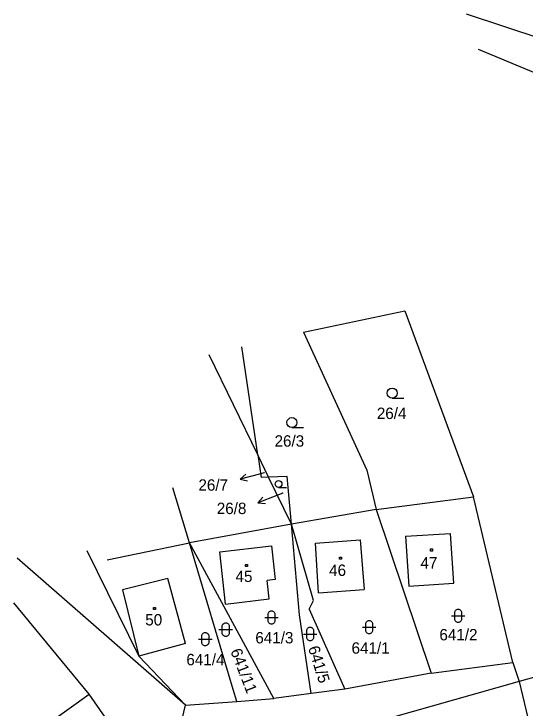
# Model space of a CAD drawing. Extents: x -866656 to -858817, y -1041816 to -1038653.
# Drawn here: x -862846 to -862769.6, y -1039578.3 to -1039474.6 of the extents above; entities that cross this region are included whole.
import ezdxf

# ---------------------------------------------------------------- set-up
doc = ezdxf.new("R2010")
doc.units = 0
doc.layers.add('Vrstva 1', color=7, linetype='Continuous')

msp = doc.modelspace()

# ---------------------------------------------------------------- linework, layer by layer
at = {"layer": 'Vrstva 1'}
for p, q in [((-862778.44, -1039474.55), (-862761.2, -1039480.26)), ((-862764.34, -1039484.99), (-862776.6, -1039479.89)), ((-862802.75, -1039522.09), (-862787.6, -1039518.92)), ((-862787.6, -1039518.92), (-862777.37, -1039546.69)), ((-862802.75, -1039522.09), (-862793.29, -1039542.71)), ((-862809.57, -1039540.42), (-862811.95, -1039524.3)), ((-862809.57, -1039540.42), (-862816.84, -1039525.48)), ((-862789.5, -1039531.95), (-862787.75, -1039531.95)), ((-862804.47, -1039536.35), (-862802.72, -1039536.35)), ((-862809.57, -1039540.42), (-862809.07, -1039543.79)), ((-862807.95, -1039543.75), (-862809.57, -1039540.42)), ((-862809.3, -1039543.29), (-862812.2, -1039544.08)), ((-862812.2, -1039544.08), (-862811.36, -1039543.33)), ((-862808.63, -1039543.11), (-862809.3, -1039543.29)), ((-862793.29, -1039542.71), (-862791.88, -1039548.6)), ((-862812.2, -1039544.08), (-862811.1, -1039544.3)), ((-862807.95, -1039543.75), (-862809.07, -1039543.79)), ((-862805.16, -1039543.67), (-862807.95, -1039543.75)), ((-862804.53, -1039550.78), (-862807.95, -1039543.75)), ((-862804.53, -1039550.78), (-862805.16, -1039543.67)), ((-862819.74, -1039553.58), (-862822.26, -1039545.37)), ((-862806.46, -1039545.28), (-862805.29, -1039545.28)), ((-862806.74, -1039546.49), (-862809.54, -1039547.57)), ((-862805.8, -1039546.13), (-862806.74, -1039546.49)), ((-862809.54, -1039547.57), (-862808.79, -1039546.74)), ((-862791.88, -1039548.6), (-862777.37, -1039546.69)), ((-862771.45, -1039571.44), (-862777.37, -1039546.69)), ((-862809.54, -1039547.57), (-862808.43, -1039547.68)), ((-862791.88, -1039548.6), (-862804.53, -1039550.78)), ((-862791.88, -1039548.6), (-862783.68, -1039573.04)), ((-862804.53, -1039550.78), (-862819.74, -1039553.58)), ((-862803.32, -1039564.33), (-862804.53, -1039550.78)), ((-862801.24, -1039562.16), (-862804.53, -1039550.78)), ((-862787.49, -1039552.58), (-862780.78, -1039552.17)), ((-862787.49, -1039552.58), (-862787.03, -1039560.05)), ((-862780.31, -1039559.61), (-862780.78, -1039552.17)), ((-862832.08, -1039556.11), (-862819.74, -1039553.58)), ((-862807.16, -1039576.83), (-862819.74, -1039553.58)), ((-862813.23, -1039575.5), (-862819.74, -1039553.58)), ((-862800.97, -1039553.61), (-862794.28, -1039553.12)), ((-862800.48, -1039561.05), (-862800.97, -1039553.61)), ((-862794.28, -1039553.12), (-862793.69, -1039560.56)), ((-862835.11, -1039554.73), (-862827.31, -1039570.49)), ((-862815.23, -1039554.93), (-862807.5, -1039554.02)), ((-862807.5, -1039554.02), (-862806.96, -1039559.06)), ((-862783.76, -1039554.49), (-862783.46, -1039554.49)), ((-862783.76, -1039554.79), (-862783.76, -1039554.49)), ((-862783.46, -1039554.79), (-862783.76, -1039554.79)), ((-862783.46, -1039554.49), (-862783.46, -1039554.79)), ((-862814.37, -1039562.74), (-862815.23, -1039554.93)), ((-862797.35, -1039555.73), (-862797.05, -1039555.73)), ((-862797.35, -1039556.03), (-862797.35, -1039555.73)), ((-862797.05, -1039555.73), (-862797.05, -1039556.03)), ((-862820.36, -1039577.84), (-862845.48, -1039555.88)), ((-862811.41, -1039556.79), (-862811.11, -1039556.79)), ((-862811.41, -1039557.09), (-862811.41, -1039556.79)), ((-862811.11, -1039556.79), (-862811.11, -1039557.09)), ((-862797.05, -1039556.03), (-862797.35, -1039556.03)), ((-862811.11, -1039557.09), (-862811.41, -1039557.09)), ((-862823.02, -1039558.9), (-862829.78, -1039560.59)), ((-862820.38, -1039568.59), (-862823.02, -1039558.9)), ((-862806.96, -1039559.06), (-862808.17, -1039559.2)), ((-862807.86, -1039561.95), (-862808.17, -1039559.2)), ((-862787.03, -1039560.05), (-862780.31, -1039559.61)), ((-862829.78, -1039560.59), (-862827.31, -1039570.49)), ((-862800.48, -1039561.05), (-862793.69, -1039560.56)), ((-862814.37, -1039562.74), (-862807.86, -1039561.95)), ((-862834.77, -1039576.2), (-862845.99, -1039562.53)), ((-862801.88, -1039563.49), (-862801.24, -1039562.16)), ((-862825.16, -1039563.25), (-862824.86, -1039563.25)), ((-862825.16, -1039563.55), (-862825.16, -1039563.25)), ((-862824.86, -1039563.55), (-862825.16, -1039563.55)), ((-862824.86, -1039563.25), (-862824.86, -1039563.55)), ((-862808.03, -1039564.13), (-862807.93, -1039563.93)), ((-862808.03, -1039565.33), (-862808.03, -1039564.13)), ((-862807.93, -1039563.93), (-862807.83, -1039563.83)), ((-862807.83, -1039563.83), (-862807.63, -1039563.73)), ((-862807.63, -1039563.73), (-862807.43, -1039563.73)), ((-862807.43, -1039563.73), (-862807.23, -1039563.83)), ((-862807.23, -1039563.83), (-862807.13, -1039563.93)), ((-862807.13, -1039563.93), (-862807.03, -1039564.13)), ((-862807.03, -1039564.13), (-862807.03, -1039565.33)), ((-862801.88, -1039563.49), (-862796.56, -1039575.42)), ((-862780.15, -1039563.88), (-862780.05, -1039563.68)), ((-862780.15, -1039565.08), (-862780.15, -1039563.88)), ((-862780.05, -1039563.68), (-862779.95, -1039563.58)), ((-862779.95, -1039563.58), (-862779.75, -1039563.48)), ((-862779.75, -1039563.48), (-862779.55, -1039563.48)), ((-862779.55, -1039563.48), (-862779.35, -1039563.58)), ((-862779.35, -1039563.58), (-862779.25, -1039563.68)), ((-862779.25, -1039563.68), (-862779.15, -1039563.88)), ((-862779.15, -1039563.88), (-862779.15, -1039565.08)), ((-862808.53, -1039564.73), (-862806.53, -1039564.73)), ((-862801.59, -1039576.09), (-862803.32, -1039564.33)), ((-862793.23, -1039565.28), (-862793.03, -1039565.18)), ((-862793.03, -1039565.18), (-862792.83, -1039565.18)), ((-862792.83, -1039565.18), (-862792.63, -1039565.28)), ((-862780.65, -1039564.48), (-862778.65, -1039564.48)), ((-862780.05, -1039565.28), (-862780.15, -1039565.08)), ((-862779.15, -1039565.08), (-862779.25, -1039565.28)), ((-862814.86, -1039565.94), (-862814.76, -1039565.74)), ((-862814.86, -1039567.14), (-862814.86, -1039565.94)), ((-862814.76, -1039565.74), (-862814.66, -1039565.64)), ((-862814.66, -1039565.64), (-862814.46, -1039565.54)), ((-862814.46, -1039565.54), (-862814.26, -1039565.54)), ((-862814.26, -1039565.54), (-862814.06, -1039565.64)), ((-862814.06, -1039565.64), (-862813.96, -1039565.74)), ((-862813.96, -1039565.74), (-862813.86, -1039565.94)), ((-862813.86, -1039565.94), (-862813.86, -1039567.14)), ((-862807.93, -1039565.53), (-862808.03, -1039565.33)), ((-862807.83, -1039565.63), (-862807.93, -1039565.53)), ((-862807.63, -1039565.73), (-862807.83, -1039565.63)), ((-862807.43, -1039565.73), (-862807.63, -1039565.73)), ((-862807.23, -1039565.63), (-862807.43, -1039565.73)), ((-862807.13, -1039565.53), (-862807.23, -1039565.63)), ((-862807.03, -1039565.33), (-862807.13, -1039565.53)), ((-862802.03, -1039566.29), (-862801.83, -1039566.19)), ((-862801.83, -1039566.19), (-862801.63, -1039566.19)), ((-862801.63, -1039566.19), (-862801.43, -1039566.29)), ((-862793.93, -1039566.18), (-862791.93, -1039566.18)), ((-862793.43, -1039565.58), (-862793.33, -1039565.38)), ((-862793.43, -1039566.78), (-862793.43, -1039565.58)), ((-862793.33, -1039565.38), (-862793.23, -1039565.28)), ((-862792.63, -1039565.28), (-862792.53, -1039565.38)), ((-862792.53, -1039565.38), (-862792.43, -1039565.58)), ((-862792.43, -1039565.58), (-862792.43, -1039566.78)), ((-862779.95, -1039565.38), (-862780.05, -1039565.28)), ((-862779.75, -1039565.48), (-862779.95, -1039565.38)), ((-862779.55, -1039565.48), (-862779.75, -1039565.48)), ((-862779.35, -1039565.38), (-862779.55, -1039565.48)), ((-862779.25, -1039565.28), (-862779.35, -1039565.38)), ((-862817.9, -1039567.35), (-862817.8, -1039567.15)), ((-862817.8, -1039567.15), (-862817.7, -1039567.05)), ((-862817.7, -1039567.05), (-862817.5, -1039566.95)), ((-862817.5, -1039566.95), (-862817.3, -1039566.95)), ((-862817.3, -1039566.95), (-862817.1, -1039567.05)), ((-862817.1, -1039567.05), (-862817, -1039567.15)), ((-862817, -1039567.15), (-862816.9, -1039567.35)), ((-862815.36, -1039566.54), (-862813.36, -1039566.54)), ((-862814.76, -1039567.34), (-862814.86, -1039567.14)), ((-862813.86, -1039567.14), (-862813.96, -1039567.34)), ((-862802.73, -1039567.19), (-862800.73, -1039567.19)), ((-862802.23, -1039566.59), (-862802.13, -1039566.39)), ((-862802.23, -1039567.79), (-862802.23, -1039566.59)), ((-862802.13, -1039566.39), (-862802.03, -1039566.29)), ((-862801.43, -1039566.29), (-862801.33, -1039566.39)), ((-862801.33, -1039566.39), (-862801.23, -1039566.59)), ((-862801.23, -1039566.59), (-862801.23, -1039567.79)), ((-862793.33, -1039566.98), (-862793.43, -1039566.78)), ((-862793.23, -1039567.08), (-862793.33, -1039566.98)), ((-862793.03, -1039567.18), (-862793.23, -1039567.08)), ((-862792.83, -1039567.18), (-862793.03, -1039567.18)), ((-862792.63, -1039567.08), (-862792.83, -1039567.18)), ((-862792.53, -1039566.98), (-862792.63, -1039567.08)), ((-862792.43, -1039566.78), (-862792.53, -1039566.98)), ((-862818.4, -1039567.95), (-862816.4, -1039567.95)), ((-862817.9, -1039568.55), (-862817.9, -1039567.35)), ((-862816.9, -1039567.35), (-862816.9, -1039568.55)), ((-862814.66, -1039567.44), (-862814.76, -1039567.34)), ((-862814.46, -1039567.54), (-862814.66, -1039567.44)), ((-862814.26, -1039567.54), (-862814.46, -1039567.54)), ((-862814.06, -1039567.44), (-862814.26, -1039567.54)), ((-862813.96, -1039567.34), (-862814.06, -1039567.44)), ((-862802.13, -1039567.99), (-862802.23, -1039567.79)), ((-862802.03, -1039568.09), (-862802.13, -1039567.99)), ((-862801.83, -1039568.19), (-862802.03, -1039568.09)), ((-862801.63, -1039568.19), (-862801.83, -1039568.19)), ((-862801.43, -1039568.09), (-862801.63, -1039568.19)), ((-862801.33, -1039567.99), (-862801.43, -1039568.09)), ((-862801.23, -1039567.79), (-862801.33, -1039567.99)), ((-862820.38, -1039568.59), (-862827.31, -1039570.49)), ((-862817.8, -1039568.75), (-862817.9, -1039568.55)), ((-862817.7, -1039568.85), (-862817.8, -1039568.75)), ((-862817.5, -1039568.95), (-862817.7, -1039568.85)), ((-862817.3, -1039568.95), (-862817.5, -1039568.95)), ((-862817.1, -1039568.85), (-862817.3, -1039568.95)), ((-862817, -1039568.75), (-862817.1, -1039568.85)), ((-862816.9, -1039568.55), (-862817, -1039568.75)), ((-862751.37, -1039568.89), (-862770.51, -1039574.3)), ((-862827.31, -1039570.49), (-862820.36, -1039577.84)), ((-862783.68, -1039573.04), (-862771.45, -1039571.44)), ((-862771.45, -1039571.44), (-862770.51, -1039574.3)), ((-862783.68, -1039573.04), (-862796.56, -1039575.42)), ((-862770.51, -1039574.3), (-862789.82, -1039579.76)), ((-862770.51, -1039574.3), (-862765.99, -1039593.51)), ((-862812.71, -1039577.25), (-862813.23, -1039575.5)), ((-862796.56, -1039575.42), (-862801.59, -1039576.09)), ((-862840.39, -1039580.21), (-862834.77, -1039576.2)), ((-862812.5, -1039607.85), (-862834.77, -1039576.2)), ((-862801.59, -1039576.09), (-862807.16, -1039576.83)), ((-862820.36, -1039577.84), (-862812.71, -1039577.25)), ((-862812.71, -1039577.25), (-862807.16, -1039576.83)), ((-862821.31, -1039581.76), (-862820.36, -1039577.84))]:
    msp.add_line(p, q, dxfattribs=at)
for centre, radius in [((-862789.5, -1039531.2), 0.75), ((-862804.47, -1039535.6), 0.75), ((-862806.46, -1039544.78), 0.503)]:
    msp.add_circle(centre, radius, dxfattribs=at)

# ---------------------------------------------------------------- texts
for s, height, p in [('26/4', 1.7, (-862791.79, -1039535.07)), ('26/3', 1.7, (-862807.06, -1039539.2)), ('26/7', 0.1, (-862808.77, -1039543.11)), ('26/7', 1.7, (-862818.43, -1039545.78)), ('26/8', 0.1, (-862805.94, -1039546.13)), ('26/8', 1.7, (-862815.69, -1039549.27)), ('47', 1.7, (-862785.27, -1039557.41)), ('46', 1.7, (-862798.91, -1039558.51)), ('45', 1.7, (-862812.89, -1039559.42)), ('50', 1.7, (-862826.37, -1039565.91)), ('641/3', 1.7, (-862809.93, -1039568.59)), ('641/2', 1.7, (-862782.44, -1039568.14)), ('641/1', 1.7, (-862795.56, -1039570.13)), ('641/4', 1.7, (-862820.23, -1039571.86))]:
    msp.add_text(s, height=height, dxfattribs=at).set_placement(p)
for s, rotation, p in [('641/5', 287.4248, (-862802.08, -1039569.26)), ('641/11', 291.1199, (-862813.68, -1039569.73))]:
    msp.add_text(s, height=1.7, rotation=rotation, dxfattribs=at).set_placement(p)

doc.saveas('drawing.dxf')
